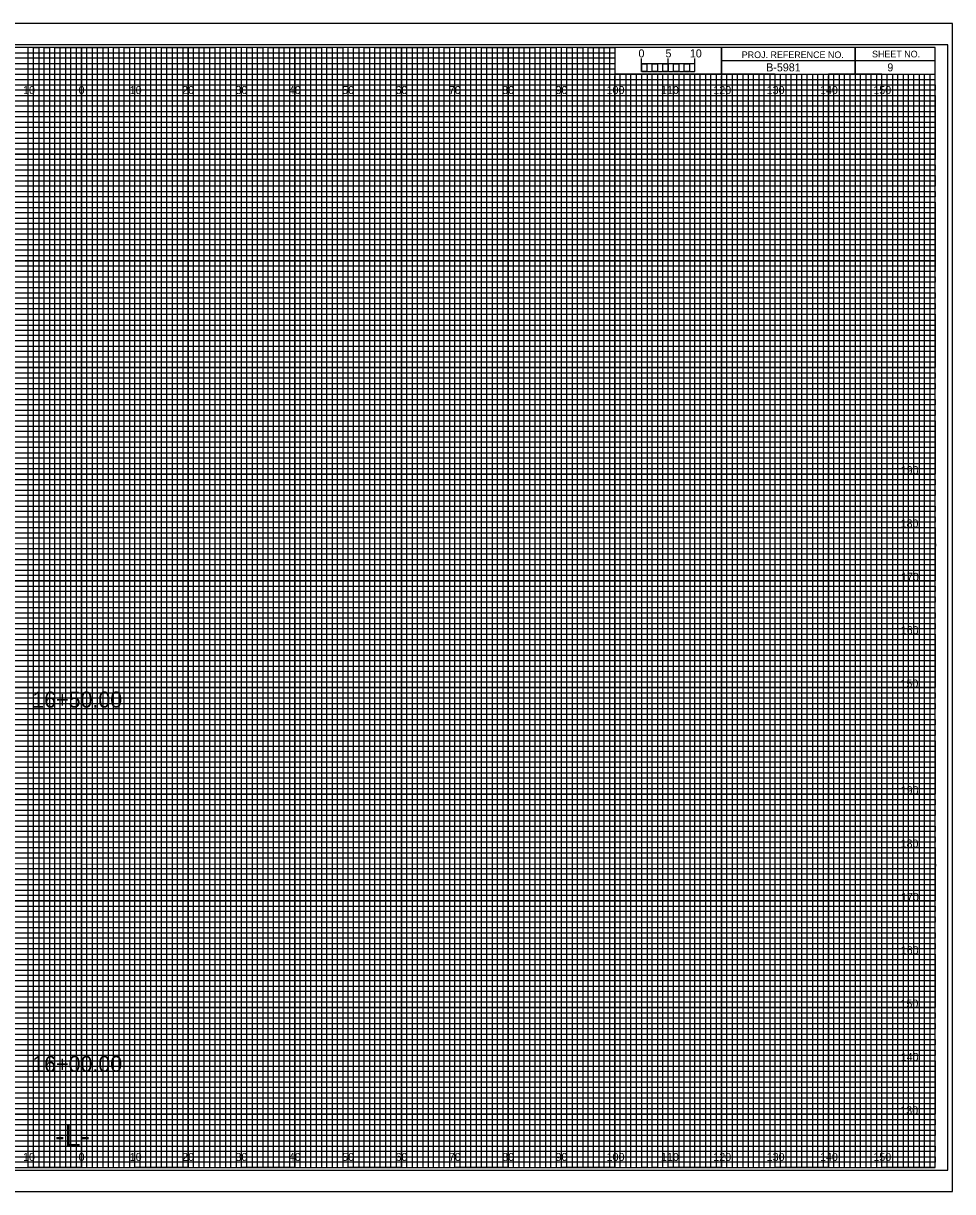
# Model space of a CAD drawing. Extents: x -13 to 323, y -5 to 4174.
# Drawn here: x 149.1 to 323.3, y 655.5 to 874.5 of the extents above; entities that cross this region are included whole.
import ezdxf

# ---------------------------------------------------------------- set-up
doc = ezdxf.new("R2010")
doc.units = 0
for name, color, linetype in [('Exist Cross Section Cell', 7, 'Continuous'), ('Exist XS Center Line Elevation Label', 7, 'Continuous'), ('Exist XS Ground Line', 7, 'Continuous'), ('Prop CMT Concrete Structures', 7, 'Continuous'), ('Prop CMT Guardrail Graphics', 7, 'Continuous'), ('Prop CMT Pvmt Course 1', 7, 'Continuous'), ('Prop CMT Pvmt Course 2', 7, 'Continuous'), ('Prop CMT Pvmt Course 3', 7, 'Continuous'), ('Prop CMT Pvmt Surface', 7, 'Continuous'), ('Prop CMT Shld Paved Course 1', 7, 'Continuous'), ('Prop CMT Shld Paved Course 2', 7, 'Continuous'), ('Prop CMT Shld Paved Course 3', 7, 'Continuous'), ('Prop CMT Subgrade Earthwork', 7, 'Continuous'), ('Prop XS Ditch Standard Text', 7, 'Continuous'), ('Prop XS SE Text', 7, 'Continuous'), ('Prop XS Side Slope Text', 7, 'Continuous'), ('Scratch_Level_0', 7, 'Continuous')]:
    doc.layers.add(name, color=color, linetype=linetype)

msp = doc.modelspace()

# ---------------------------------------------------------------- linework, layer by layer
at = {"layer": 'Exist XS Center Line Elevation Label'}
for points in [[(145, 660), (155, 660), (155, 870), (165, 870), (165, 660), (175, 660), (175, 870), (185, 870), (185, 660), (195, 660), (195, 870), (205, 870), (205, 660), (215, 660), (215, 870), (225, 870), (225, 660), (235, 660), (235, 870), (245, 870), (245, 660), (255, 660), (255, 870), (259.93, 870), (260, 870), (260, 865), (264.99, 865), (264.99, 660), (275, 660), (275, 865), (285, 865), (285, 660), (295, 660), (295, 865), (305, 865), (305, 660), (315, 660), (315, 865)], [(0, 865), (275, 865)], [(0, 845), (320, 845), (320, 855), (0, 855)], [(0, 825), (320, 825), (320, 835), (0, 835)], [(0, 805), (320, 805), (320, 815), (0, 815)], [(0, 785), (320, 785), (320, 795), (0, 795)], [(0, 765), (320, 765), (320, 775), (0, 775)], [(0, 745), (320, 745), (320, 755), (0, 755)], [(0, 725), (320, 725), (320, 735), (0, 735)], [(0, 705), (320, 705), (320, 715), (0, 715)], [(0, 685), (320, 685), (320, 695), (0, 695)], [(0, 665), (320, 665), (320, 675), (0, 675)]]:
    msp.add_lwpolyline(points, dxfattribs=at)
at = {"layer": 'Exist XS Ground Line'}
for p, q in [((150, 870), (140, 870)), ((150, 660), (150, 870)), ((170, 870), (160, 870)), ((160, 870), (160, 660)), ((170, 660), (170, 870)), ((190, 870), (180, 870)), ((180, 870), (180, 660)), ((190, 660), (190, 870)), ((210, 870), (200, 870)), ((200, 870), (200, 660)), ((210, 660), (210, 870)), ((230, 870), (220, 870)), ((220, 870), (220, 660)), ((230, 660), (230, 870)), ((250, 870), (240, 870)), ((240, 870), (240, 660)), ((250, 660), (250, 870)), ((260, 870), (260, 660)), ((270, 660), (270, 865)), ((290, 865), (280, 865)), ((280, 865), (280, 660)), ((290, 660), (290, 865)), ((310, 865), (300, 865)), ((300, 865), (300, 660)), ((310, 660), (310, 865)), ((160, 660), (150, 660)), ((180, 660), (170, 660)), ((200, 660), (190, 660)), ((220, 660), (210, 660)), ((240, 660), (230, 660)), ((260, 660), (250, 660)), ((280, 660), (270, 660)), ((300, 660), (290, 660)), ((320, 660), (310, 660)), ((320, 660), (320, 660))]:
    msp.add_line(p, q, dxfattribs=at)
for points in [[(0, 860), (320, 860), (320, 850), (0, 850)], [(0, 840), (320, 840), (320, 830), (0, 830)], [(0, 820), (320, 820), (320, 810), (0, 810)], [(0, 800), (320, 800), (320, 790), (0, 790)], [(0, 780), (320, 780), (320, 770), (0, 770)], [(0, 760), (320, 760), (320, 750), (0, 750)], [(0, 740), (320, 740), (320, 730), (0, 730)], [(0, 720), (320, 720), (320, 710), (0, 710)], [(0, 700), (320, 700), (320, 690), (0, 690)], [(0, 680), (320, 680), (320, 670), (0, 670)]]:
    msp.add_lwpolyline(points, dxfattribs=at)
at = {"layer": 'Prop CMT Pvmt Course 1'}
for p, q in [((323.3, 874.5), (-13.4, 874.5)), ((-13.4, 655.5), (323.3, 655.5))]:
    msp.add_line(p, q, dxfattribs=at)
at = {"layer": 'Prop CMT Pvmt Course 2'}
msp.add_lwpolyline([(-13.4, 655.5), (323.3, 655.5), (323.3, 874.5), (-13.4, 874.5)], close=True, dxfattribs=at)
at = {"layer": 'Prop CMT Pvmt Course 3'}
msp.add_lwpolyline([(-10.8, 659.5), (322.4, 659.5), (322.4, 870.5), (-10.8, 870.5)], close=True, dxfattribs=at)
at = {"layer": 'Prop CMT Shld Paved Course 1'}
for p, q in [((305, 870), (305, 865)), ((305, 865), (305, 870)), ((280, 867.5), (280, 865)), ((320, 867.49), (280, 867.49)), ((280, 865), (320, 865))]:
    msp.add_line(p, q, dxfattribs=at)
for points in [[(320, 870), (0, 870), (0, 660), (320, 660)], [(280, 870), (260, 870), (260, 865.03), (280, 865.03)], [(320, 870), (280, 870), (280, 865), (320, 865)]]:
    msp.add_lwpolyline(points, close=True, dxfattribs=at)
at = {"layer": 'Prop CMT Shld Paved Course 2'}
for p, q in [((267, 865), (266.01, 865)), ((266.01, 865), (266.01, 660)), ((267, 660), (267, 865)), ((269, 865), (268, 865)), ((268, 865), (268, 660)), ((269, 660), (269, 865)), ((266.01, 660), (265, 660)), ((268, 660), (267, 660))]:
    msp.add_line(p, q, dxfattribs=at)
for points in [[(150, 660), (151, 660), (151, 870), (152, 870), (152, 660)], [(152, 660), (153, 660), (153, 870), (154, 870), (154, 660)], [(155, 660), (156, 660), (156, 870), (157, 870), (157, 660)], [(157, 660), (158, 660), (158, 870), (159, 870), (159, 660)], [(160, 660), (161, 660), (161, 870), (162, 870), (162, 660)], [(162, 660), (163, 660), (163, 870), (164, 870), (164, 660)], [(165, 660), (166, 660), (166, 870), (167, 870), (167, 660)], [(167, 660), (168, 660), (168, 870), (169, 870), (169, 660)], [(170, 660), (171, 660), (171, 870), (172, 870), (172, 660)], [(172, 660), (173, 660), (173, 870), (174, 870), (174, 660)], [(175, 660), (176, 660), (176, 870), (177, 870), (177, 660)], [(177, 660), (178, 660), (178, 870), (179, 870), (179, 660)], [(180, 660), (181, 660), (181, 870), (182, 870), (182, 660)], [(182, 660), (183, 660), (183, 870), (184, 870), (184, 660)], [(185, 660), (186, 660), (186, 870), (187, 870), (187, 660)], [(187, 660), (188, 660), (188, 870), (189, 870), (189, 660)], [(190, 660), (191, 660), (191, 870), (192, 870), (192, 660)], [(192, 660), (193, 660), (193, 870), (194, 870), (194, 660)], [(195, 660), (196, 660), (196, 870), (197, 870), (197, 660)], [(197, 660), (198, 660), (198, 870), (199, 870), (199, 660)], [(200, 660), (201, 660), (201, 870), (202, 870), (202, 660)], [(202, 660), (203, 660), (203, 870), (204, 870), (204, 660)], [(205, 660), (206, 660), (206, 870), (207, 870), (207, 660)], [(207, 660), (208, 660), (208, 870), (209, 870), (209, 660)], [(210, 660), (211, 660), (211, 870), (212, 870), (212, 660)], [(212, 660), (213, 660), (213, 870), (214, 870), (214, 660)], [(215, 660), (216, 660), (216, 870), (217, 870), (217, 660)], [(217, 660), (218, 660), (218, 870), (219, 870), (219, 660)], [(220, 660), (221, 660), (221, 870), (222, 870), (222, 660)], [(222, 660), (223, 660), (223, 870), (224, 870), (224, 660)], [(225, 660), (226, 660), (226, 870), (227, 870), (227, 660)], [(227, 660), (228, 660), (228, 870), (229, 870), (229, 660)], [(230, 660), (231, 660), (231, 870), (232, 870), (232, 660)], [(232, 660), (233, 660), (233, 870), (234, 870), (234, 660)], [(235, 660), (236, 660), (236, 870), (237, 870), (237, 660)], [(237, 660), (238, 660), (238, 870), (239, 870), (239, 660)], [(240, 660), (241, 660), (241, 870), (242, 870), (242, 660)], [(242, 660), (243, 660), (243, 870), (244, 870), (244, 660)], [(245, 660), (246, 660), (246, 870), (247, 870), (247, 660)], [(247, 660), (248, 660), (248, 870), (249, 870), (249, 660)], [(250, 660), (251, 660), (251, 870), (252, 870), (252, 660)], [(252, 660), (253, 660), (253, 870), (254, 870), (254, 660)], [(255, 660), (256, 660), (256, 870), (257, 870), (257, 660)], [(257, 660), (258, 660), (258, 870), (259, 870), (259, 660)], [(260, 660), (261, 660), (261, 865), (262.02, 865), (262.02, 660)], [(262, 660), (263, 660), (263, 865), (263.99, 865), (263.99, 660)], [(270, 660), (270.98, 660), (270.98, 865), (272, 865), (272, 660)], [(272, 660), (273, 660), (273, 865), (274.05, 865), (274.05, 660)], [(275, 660), (276, 660), (276, 865), (277, 865), (277, 660)], [(277, 660), (278, 660), (278, 865), (279, 865), (279, 660)], [(280, 660), (281, 660), (281, 865), (282, 865), (282, 660)], [(282, 660), (283, 660), (283, 865), (284, 865), (284, 660)], [(285, 660), (286, 660), (286, 865), (287, 865), (287, 660)], [(287, 660), (288, 660), (288, 865), (289, 865), (289, 660)], [(290, 660), (291, 660), (291, 865), (292, 865), (292, 660)], [(292, 660), (293, 660), (293, 865), (294, 865), (294, 660)], [(295, 660), (296, 660), (296, 865), (297, 865), (297, 660)], [(297, 660), (298, 660), (298, 865), (299, 865), (299, 660)], [(300, 660), (301, 660), (301, 865), (302, 865), (302, 660)], [(302, 660), (303, 660), (303, 865), (304, 865), (304, 660)], [(305, 660), (306, 660), (306, 865), (307, 865), (307, 660)], [(307, 660), (308, 660), (308, 865), (309, 865), (309, 660)], [(310, 660), (311, 660), (311, 865), (312, 865), (312, 660)], [(312, 660), (313, 660), (313, 865), (314, 865), (314, 660)], [(315, 660), (316, 660), (316, 865), (317, 865), (317, 660)], [(317, 660), (318, 660), (318, 865), (319, 865), (319, 660)]]:
    msp.add_lwpolyline(points, dxfattribs=at)
at = {"layer": 'Prop CMT Shld Paved Course 3'}
for p, q in [((265, 865.49), (265, 867.9)), ((265, 866.9), (265, 867.9)), ((270, 865.49), (270, 867.9)), ((275, 865.49), (275, 867.9)), ((275, 866.9), (275, 867.9))]:
    msp.add_line(p, q, dxfattribs=at)
for points in [[(275, 866.9), (265, 866.9), (265, 865.49), (275, 865.49)], [(265, 866.9), (266, 866.9), (266, 865.49), (265, 865.49)], [(267, 866.9), (268, 866.9), (268, 865.49), (267, 865.49)], [(269, 866.9), (270, 866.9), (270, 865.49), (269, 865.49)], [(271, 866.9), (272, 866.9), (272, 865.49), (271, 865.49)], [(273, 866.9), (274, 866.9), (274, 865.49), (273, 865.49)]]:
    msp.add_lwpolyline(points, close=True, dxfattribs=at)
at = {"layer": 'Prop CMT Subgrade Earthwork'}
for p, q in [((150, 660), (150, 870)), ((160, 660), (160, 870)), ((170, 660), (170, 870)), ((180, 660), (180, 870)), ((190, 660), (190, 870)), ((200, 660), (200, 870)), ((210, 660), (210, 870)), ((220, 660), (220, 870)), ((230, 660), (230, 870)), ((240, 660), (240, 870)), ((250, 660), (250, 870)), ((260, 660), (260, 864.69)), ((270, 660), (270, 864.69)), ((280, 660), (280, 864.69)), ((290, 660), (290, 864.69)), ((300, 660), (300, 864.69)), ((310, 660), (310, 864.69)), ((0, 860), (320, 860)), ((0, 850), (320, 850)), ((0, 840), (320, 840)), ((0, 830), (320, 830)), ((0, 820), (320, 820)), ((0, 810), (320, 810)), ((0, 800), (320, 800)), ((0, 790), (320, 790)), ((0, 780), (320, 780)), ((0, 770), (320, 770)), ((0, 760), (320, 760)), ((0, 750), (320, 750)), ((0, 740), (320, 740)), ((0, 730), (320, 730)), ((0, 720), (320, 720)), ((0, 710), (320, 710)), ((0, 700), (320, 700)), ((0, 690), (320, 690)), ((0, 680), (320, 680)), ((0, 670), (320, 670))]:
    msp.add_line(p, q, dxfattribs=at)
at = {"layer": 'Scratch_Level_0'}
for p, q in [((0, 869), (260, 869)), ((260, 867.98), (0, 867.98)), ((260, 869), (260, 867.98)), ((0, 867), (260, 867)), ((260, 865.89), (0, 865.89)), ((260, 867), (260, 865.89)), ((0, 864), (320, 864))]:
    msp.add_line(p, q, dxfattribs=at)
for points in [[(0, 863), (270, 863), (320, 863), (320, 862), (0, 862)], [(0, 861), (320, 861), (320, 859), (0, 859)], [(0, 858), (320, 858), (320, 857), (0, 856.98)], [(0, 856), (320, 856), (320, 854), (0, 854)], [(0, 853), (320, 853), (320, 852), (0, 852)], [(0, 851), (320, 851), (320, 849), (0, 849)], [(0, 848), (320, 848), (320, 847), (0, 847)], [(0, 846), (320, 846), (320, 844), (0, 844)], [(0, 843), (320, 843), (320, 842), (0, 842)], [(0, 841), (320, 841), (320, 839), (0, 839)], [(0, 838), (320, 838), (320, 837), (0, 837)], [(0, 836), (320, 836), (320, 833.95), (320, 833), (320, 832), (0, 832)], [(0, 834), (320, 834), (320, 833), (0, 833)], [(0, 831), (320, 831), (320, 829), (0, 829.03)], [(0, 829.03), (320, 829), (320, 828), (0, 828)], [(0, 827), (320, 827), (320, 826), (0, 826)], [(0, 824), (320, 824), (320, 823), (0, 823)], [(0, 822), (320, 822), (320, 821), (0, 821)], [(-0.07, 818.89), (320, 818.89), (320, 817.88), (-0.07, 817.88)], [(0, 817), (320, 817), (320, 816), (0, 816)], [(0, 814), (320, 814), (320, 813), (0, 813)], [(0, 812), (320, 812), (320, 811), (0, 811)], [(0, 809), (320, 809), (320, 808), (0, 808)], [(0, 807), (320, 807), (320, 806), (0, 806)], [(0, 804), (320, 804), (320, 803), (0, 803)], [(0, 802), (320, 802), (320, 801), (0, 801)], [(0, 799), (320, 799), (319.99, 797.98), (0, 798)], [(0, 797), (320, 797), (320, 796), (0, 796)], [(0, 794), (320, 794), (320, 793), (0, 793)], [(0, 792), (320, 792), (320, 791), (0, 791)], [(0, 789), (320, 789), (320, 788), (0, 788)], [(0, 787), (320, 787), (320, 786), (0, 786)], [(0, 784), (320, 784), (320, 783), (0, 783)], [(0, 782), (320, 782), (320, 781), (0, 781)], [(0, 779), (320, 779), (320, 778), (0, 778)], [(0, 776.99), (320.07, 776.91), (320, 776), (0, 776)], [(0, 774), (320, 774), (320, 773), (0, 773)], [(0, 772), (320, 772), (320, 771), (0, 771)], [(0, 769), (320, 769), (320, 768), (0, 768)], [(0, 767), (320, 767), (320, 766), (0, 766)], [(0, 764), (320, 764), (320, 763), (0, 763)], [(0, 762), (320, 762), (320, 761), (0, 761)], [(0, 759), (320, 759), (320, 758), (0, 758)], [(0, 757), (320, 757), (320, 756), (0, 756)], [(0, 754), (320, 754), (320, 753), (0, 753)], [(0, 752), (320, 752), (320, 751), (0, 751)], [(0, 749), (320, 749), (320, 748), (0, 748)], [(0, 747), (320, 747), (320, 746), (0, 746)], [(0, 744), (320, 744), (320, 743), (0, 743)], [(0, 742), (320, 742), (320, 741), (0, 741)], [(0, 739), (320, 739), (319.99, 737.98), (0, 738)], [(0, 737), (320, 737), (320, 736), (0, 736)], [(0, 734), (320, 734), (320, 733), (0, 733)], [(0, 732), (320, 732), (320, 731), (0, 731)], [(0, 729), (320, 729), (320, 728), (0, 728)], [(0, 727), (320, 727), (320, 726), (0, 726)], [(0, 724), (320, 724), (320, 723), (0, 723)], [(0, 722), (320, 722), (320, 721), (0, 721)], [(0, 719), (320, 719), (320, 718), (0, 718)], [(0, 716.99), (320.07, 716.91), (320, 716), (0, 716)], [(0, 714), (320, 714), (320, 713), (0, 713)], [(0, 712), (320, 712), (320, 711), (0, 711)], [(0, 709), (320, 709), (320, 708), (0, 708)], [(0, 707), (320, 707), (320, 706), (0, 706)], [(0, 704), (320, 704), (320, 703), (0, 703)], [(0, 702), (320, 702), (320, 701), (0, 701)], [(0, 699), (320, 699), (320, 698), (0, 698)], [(0, 697), (320, 697), (320, 696), (0, 696)], [(0, 694), (320, 694), (320, 693), (0, 693)], [(0, 692), (320, 692), (320, 691), (0, 691)], [(0, 689), (320, 689), (320, 688), (0, 688)], [(0, 687), (320, 687), (320, 686), (0, 686)], [(0, 684), (320, 684), (320, 683), (0, 683)], [(0, 682), (320, 682), (320, 681), (0, 681)], [(0, 679), (320, 679), (320, 678), (0, 678)], [(0, 677), (320, 677), (320, 676), (0, 676)], [(0, 674), (320, 674), (320, 673), (0, 673)], [(0, 672), (320, 672), (320, 671), (0, 671)], [(0, 669), (320, 669), (320, 668), (0, 668)], [(0, 667), (320, 667), (320, 666), (0, 666)], [(0, 664), (320, 664), (320, 663), (0, 663)], [(0, 662), (320, 662), (320, 661), (0, 661)]]:
    msp.add_lwpolyline(points, dxfattribs=at)

# ---------------------------------------------------------------- texts
at = {"layer": 'Exist Cross Section Cell'}
for s, p in [('10', (149.04, 861.25)), ('0', (159.45, 861.25)), ('0', (159.45, 861.25)), ('10', (169.04, 861.25)), ('20', (178.86, 861.25)), ('30', (188.86, 861.25)), ('40', (198.86, 861.25)), ('50', (208.86, 861.25)), ('60', (218.86, 861.25)), ('70', (228.86, 861.25)), ('80', (238.86, 861.25)), ('90', (248.86, 861.25)), ('100', (258.44, 861.25)), ('110', (268.62, 861.25)), ('120', (278.44, 861.25)), ('130', (288.44, 861.25)), ('140', (298.44, 861.25)), ('150', (308.44, 861.25)), ('10', (149.04, 661.25)), ('0', (159.45, 661.25)), ('0', (159.45, 661.25)), ('10', (169.04, 661.25)), ('20', (178.86, 661.25)), ('30', (188.86, 661.25)), ('40', (198.86, 661.25)), ('50', (208.86, 661.25)), ('60', (218.86, 661.25)), ('70', (228.86, 661.25)), ('80', (238.86, 661.25)), ('90', (248.86, 661.25)), ('100', (258.44, 661.25)), ('110', (268.62, 661.25)), ('120', (278.44, 661.25)), ('130', (288.44, 661.25)), ('140', (298.44, 661.25)), ('150', (308.44, 661.25))]:
    msp.add_text(s, height=1.5, dxfattribs=at).set_placement(p)
at = {"layer": 'Prop CMT Concrete Structures'}
for s, p in [('16+50.00', (150.77, 746.24)), ('16+00.00', (150.77, 677.94))]:
    msp.add_text(s, height=3, dxfattribs=at).set_placement(p)
at = {"layer": 'Prop CMT Guardrail Graphics'}
for s, p in [('190', (313.57, 790)), ('180', (313.55, 780)), ('170', (313.61, 770)), ('160', (313.57, 760)), ('150', (313.52, 750)), ('190', (313.57, 730)), ('180', (313.55, 720)), ('170', (313.61, 710)), ('160', (313.57, 700)), ('150', (313.52, 690)), ('140', (313.57, 680)), ('130', (313.49, 670))]:
    msp.add_text(s, height=1.5, dxfattribs=at).set_placement(p)
at = {"layer": 'Prop CMT Pvmt Surface'}
for s, p in [('5', (269.47, 868.12)), ('10', (274.04, 868.12))]:
    msp.add_text(s, height=1.5, dxfattribs=at).set_placement(p)
at = {"layer": 'Prop CMT Shld Paved Course 1'}
for s, p in [('PROJ. REFERENCE NO.', (283.77, 867.99)), ('SHEET NO.', (308.19, 868.12))]:
    msp.add_text(s, height=1.25, dxfattribs=at).set_placement(p)
at = {"layer": 'Prop CMT Shld Paved Course 3'}
msp.add_text('0', height=1.5, dxfattribs=at).set_placement((264.41, 868.12))
at = {"layer": 'Prop XS Ditch Standard Text'}
msp.add_text('-L-', height=4, dxfattribs=at).set_placement((155.06, 664))
at = {"layer": 'Prop XS SE Text'}
msp.add_text(' B-5981', height=1.5, dxfattribs=at).set_placement((287.79, 865.5))
at = {"layer": 'Prop XS Side Slope Text'}
msp.add_text('9', height=1.5, dxfattribs=at).set_placement((311.06, 865.5))

doc.saveas('drawing.dxf')
